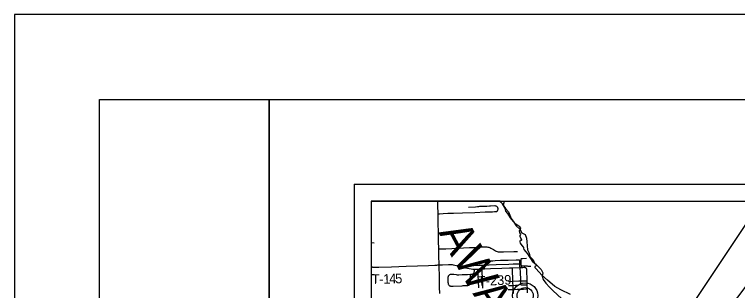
# Model space of a CAD drawing. Extents: x -12 to 34, y 0 to 22.
# Drawn here: x 0 to 4.257, y 20.374 to 22 of the extents above; entities that cross this region are included whole.
import ezdxf

# ---------------------------------------------------------------- set-up
doc = ezdxf.new("R2010")
doc.units = 0
for name, color, linetype in [('GM_X_Adjacent_County', 7, 'Continuous'), ('GM_X_Airport_Location_Class_2', 7, 'Continuous'), ('GM_X_County', 7, 'Continuous'), ('GM_X_County_Road_Text', 7, 'Continuous'), ('GM_X_Interstate_Location', 7, 'Continuous'), ('GM_X_Major_Lake', 7, 'Continuous'), ('GM_X_Major_Lake_Text', 7, 'Continuous'), ('GM_X_Major_River', 7, 'Continuous'), ('GM_X_Minor_River', 7, 'Continuous'), ('GM_X_Section', 7, 'Continuous'), ('GM_X_Township', 7, 'Continuous')]:
    doc.layers.add(name, color=color, linetype=linetype)

msp = doc.modelspace()

# ---------------------------------------------------------------- linework, layer by layer
at = {"layer": 'GM_X_Adjacent_County'}
msp.add_lwpolyline([(4.3077, 20.7695), (2.2584, 17.6954), (4.3077, 20.4)], close=True, dxfattribs=at)
at = {"layer": 'GM_X_Airport_Location_Class_2'}
for points in [[(3.2743, 20.3512), (3.2166, 20.3788), (3.1826, 20.399), (3.1387, 20.4357), (3.1057, 20.4645), (3.0716, 20.5015), (3.0667, 20.5084), (3.0652, 20.5149), (3.0677, 20.5194), (3.071, 20.5207), (3.0723, 20.5292), (3.0682, 20.5291), (3.0632, 20.5325), (3.0539, 20.5406), (3.0218, 20.5914), (3.0129, 20.6024), (3.0017, 20.617), (2.9993, 20.6241), (2.9999, 20.6294), (2.9947, 20.6323), (2.9798, 20.6534), (2.9773, 20.6606), (2.9773, 20.6665), (2.9789, 20.671), (2.9828, 20.6723), (2.9848, 20.6696), (2.9878, 20.671), (2.9848, 20.6775), (2.9773, 20.6905), (2.9771, 20.7009), (2.9804, 20.7014), (2.9819, 20.7063), (2.9761, 20.7139), (2.9738, 20.7278), (2.9789, 20.7331), (2.9817, 20.7408), (2.9754, 20.7494), (2.9529, 20.7652), (2.9376, 20.7806), (2.9215, 20.8031), (2.9049, 20.8288), (2.8931, 20.8413), (2.8916, 20.8525), (2.8855, 20.8653), (2.8738, 20.8847), (2.8638, 20.8955), (2.8606, 20.9), (2.1, 20.9), (2.1, 15.613)], [(3.2743, 20.3512), (3.2166, 20.3788), (3.1826, 20.399), (3.1387, 20.4357), (3.1057, 20.4645), (3.0716, 20.5015), (3.0667, 20.5084), (3.0652, 20.5149), (3.0677, 20.5194), (3.071, 20.5207), (3.0723, 20.5292), (3.0682, 20.5291), (3.0632, 20.5325), (3.0539, 20.5406), (3.0218, 20.5914), (3.0129, 20.6024), (3.0017, 20.617), (2.9993, 20.6241), (2.9999, 20.6294), (2.9947, 20.6323), (2.9798, 20.6534), (2.9773, 20.6606), (2.9773, 20.6665), (2.9789, 20.671), (2.9828, 20.6723), (2.9848, 20.6696), (2.9878, 20.671), (2.9848, 20.6775), (2.9773, 20.6905), (2.9771, 20.7009), (2.9804, 20.7014), (2.9819, 20.7063), (2.9761, 20.7139), (2.9738, 20.7278), (2.9789, 20.7331), (2.9817, 20.7408), (2.9754, 20.7494), (2.9529, 20.7652), (2.9376, 20.7806), (2.9215, 20.8031), (2.9049, 20.8288), (2.8931, 20.8413), (2.8916, 20.8525), (2.8855, 20.8653), (2.8738, 20.8847), (2.8638, 20.8955), (2.8606, 20.9), (2.1, 20.9), (2.1, 17.9664)]]:
    msp.add_lwpolyline(points, dxfattribs=at)
at = {"layer": 'GM_X_County'}
for points in [[(0.5, 21.5), (1.5, 21.5), (1.5, 0.5), (0.5, 0.5)], [(1.5, 21.5), (33.5, 21.5), (33.5, 0.5), (1.5, 0.5)]]:
    msp.add_lwpolyline(points, close=True, dxfattribs=at)
at = {"layer": 'GM_X_Interstate_Location'}
for radius in [0.0744, 0.0472]:
    msp.add_circle((3.0069, 20.345), radius, dxfattribs=at)
at = {"layer": 'GM_X_Major_Lake'}
msp.add_lwpolyline([(2.5037, 20.3569), (2.5028, 20.3942), (2.502, 20.447), (2.5004, 20.5249), (2.5002, 20.5371), (2.4993, 20.5682), (2.4984, 20.6191), (2.4976, 20.6645), (2.4961, 20.7203), (2.4954, 20.7668), (2.4943, 20.8263), (2.4934, 20.8751), (2.4929, 20.9)], dxfattribs=at)
at = {"layer": 'GM_X_Major_River'}
for p, q in [((2.1, 20.6568), (2.1189, 20.6561)), ((2.9316, 20.5081), (2.9768, 20.5103)), ((2.9768, 20.5103), (2.9849, 20.5106)), ((2.9093, 20.4037), (2.9358, 20.4044)), ((2.9369, 20.3813), (2.9358, 20.4044)), ((3.0166, 20.4324), (3.0176, 20.4089)), ((3.0176, 20.4089), (3.0186, 20.3839)), ((2.9072, 20.3802), (2.9369, 20.3813))]:
    msp.add_line(p, q, dxfattribs=at)
for points in [[(2.4943, 20.8263), (2.5022, 20.8268), (2.5238, 20.8282), (2.5517, 20.8293), (2.5858, 20.83), (2.6384, 20.8322), (2.7097, 20.8344), (2.7717, 20.8375), (2.7995, 20.8384), (2.815, 20.8387), (2.8274, 20.839), (2.8336, 20.8394), (2.8366, 20.8399), (2.8392, 20.8407), (2.8408, 20.8417), (2.8421, 20.8426), (2.8432, 20.8438), (2.8442, 20.8449), (2.8453, 20.8464), (2.8462, 20.8484), (2.847, 20.8504), (2.8474, 20.8535), (2.8474, 20.8557), (2.8472, 20.8575), (2.8469, 20.8596), (2.8457, 20.8625), (2.844, 20.8651), (2.8419, 20.8674), (2.8395, 20.8693), (2.8368, 20.8708), (2.8339, 20.8718), (2.8308, 20.8723), (2.8277, 20.8724), (2.8029, 20.8711), (2.7968, 20.871), (2.7813, 20.8702), (2.7473, 20.8693), (2.738, 20.8686), (2.7319, 20.868), (2.7259, 20.8665), (2.7136, 20.8653), (2.6741, 20.8631)], [(2.4984, 20.6191), (2.5033, 20.6193), (2.5404, 20.6206), (2.6796, 20.6272), (2.7074, 20.6286), (2.729, 20.6294), (2.7537, 20.6309), (2.766, 20.6312), (2.7815, 20.6311), (2.7877, 20.6306), (2.7908, 20.6301), (2.7938, 20.6294), (2.7967, 20.6285), (2.7996, 20.6273), (2.8051, 20.6245), (2.8209, 20.6152), (2.8316, 20.6089), (2.8372, 20.6062), (2.8426, 20.6039), (2.8483, 20.6023), (2.8514, 20.6018), (2.8545, 20.6015), (2.8576, 20.6015), (2.8802, 20.6025), (2.94, 20.6043), (2.9553, 20.6044), (2.961, 20.604)], [(2.9845, 20.52), (2.9842, 20.5257), (2.9835, 20.5413), (2.9834, 20.5474), (2.9829, 20.5534), (2.9829, 20.5566), (2.983, 20.558), (2.9836, 20.5597), (2.9843, 20.5611), (2.9852, 20.5622), (2.9864, 20.5632), (2.9878, 20.5636), (2.9909, 20.5638), (3.0139, 20.5641)], [(2.1, 20.5161), (2.1, 20.5161), (2.1056, 20.514), (2.1085, 20.513), (2.1128, 20.5122), (2.1181, 20.5116), (2.1273, 20.5111), (2.1458, 20.5115), (2.2202, 20.5146), (2.3071, 20.5178), (2.3723, 20.5203), (2.4375, 20.5228), (2.4747, 20.5243), (2.4872, 20.5248), (2.4934, 20.5249), (2.5004, 20.5249)], [(2.5004, 20.5249), (2.521, 20.5255), (2.5551, 20.5269), (2.5644, 20.5274), (2.5707, 20.5274), (2.577, 20.527), (2.5832, 20.5262), (2.5924, 20.5244), (2.6135, 20.5193), (2.6278, 20.5158)], [(2.6278, 20.5158), (2.6314, 20.5176), (2.6347, 20.5187), (2.6379, 20.5194), (2.6413, 20.5199), (2.6491, 20.5204), (2.7057, 20.5225), (2.7367, 20.5232), (2.7614, 20.5242), (2.7704, 20.5247)], [(2.7675, 20.5018), (2.7676, 20.506), (2.7679, 20.51), (2.7687, 20.5161), (2.7698, 20.522), (2.7704, 20.5247)], [(2.7704, 20.5247), (2.7711, 20.5273), (2.7725, 20.5314), (2.774, 20.5346), (2.7754, 20.537), (2.7773, 20.539), (2.7793, 20.5408), (2.7822, 20.5426), (2.7855, 20.5443), (2.7906, 20.5463), (2.7969, 20.5482), (2.8017, 20.5494), (2.8062, 20.5499), (2.8163, 20.5503), (2.8302, 20.5509), (2.8611, 20.5523), (2.8797, 20.5532), (2.9073, 20.5542), (2.9537, 20.5556), (2.966, 20.556), (2.9715, 20.5558), (2.9723, 20.5557), (2.973, 20.5553), (2.9735, 20.5549)], [(2.7704, 20.5247), (2.7951, 20.526), (2.8357, 20.527), (2.9109, 20.5303), (2.9357, 20.531), (2.9719, 20.5325), (2.9755, 20.5326)], [(2.9755, 20.5326), (2.9748, 20.5504), (2.9747, 20.5519), (2.9744, 20.553), (2.974, 20.5541), (2.9735, 20.5549)], [(2.9768, 20.5103), (2.9763, 20.5134), (2.9758, 20.5182), (2.9758, 20.522), (2.9755, 20.5326)], [(2.6278, 20.5158), (2.6558, 20.5089), (2.677, 20.5041), (2.6891, 20.5018), (2.6983, 20.5005), (2.705, 20.5001), (2.706, 20.5)], [(2.706, 20.5), (2.7061, 20.4944), (2.7059, 20.4864), (2.7056, 20.4833), (2.7049, 20.4803), (2.7038, 20.4774), (2.7021, 20.4748), (2.7, 20.4726), (2.6974, 20.4708), (2.6946, 20.4696), (2.6917, 20.4688), (2.6886, 20.4683), (2.6855, 20.4681), (2.6843, 20.468)], [(2.706, 20.5), (2.7075, 20.4999), (2.7199, 20.5), (2.7288, 20.5003)], [(2.7288, 20.5003), (2.7537, 20.5012), (2.7633, 20.5016), (2.7675, 20.5018)], [(2.734, 20.3896), (2.7303, 20.464), (2.729, 20.4969), (2.7288, 20.5003)], [(2.7587, 20.3884), (2.7571, 20.4239), (2.7546, 20.4804), (2.7539, 20.4959), (2.7537, 20.5012)], [(2.7675, 20.5018), (2.8036, 20.5033), (2.8688, 20.5056), (2.9153, 20.5073), (2.9316, 20.5081)], [(2.9349, 20.4295), (2.9319, 20.5015), (2.9316, 20.5081)], [(2.9808, 20.4314), (2.9791, 20.4891), (2.9783, 20.5006), (2.9779, 20.5042), (2.9774, 20.5071), (2.9768, 20.5103)], [(2.9845, 20.52), (2.9882, 20.5201), (3.0068, 20.5204), (3.0131, 20.5205), (3.0154, 20.5202), (3.0174, 20.5199), (3.0191, 20.5192), (3.0221, 20.5182), (3.0251, 20.5176), (3.0282, 20.5172), (3.0313, 20.5171), (3.0402, 20.5173)], [(2.9849, 20.5106), (2.9847, 20.515), (2.9845, 20.52)], [(2.9849, 20.5106), (2.9927, 20.511), (3.001, 20.5113), (3.004, 20.5111), (3.0056, 20.5108), (3.0073, 20.5105), (3.0085, 20.51), (3.0099, 20.5093), (3.0106, 20.5087)], [(3.0106, 20.5087), (3.0113, 20.508), (3.0125, 20.5063), (3.0131, 20.5053), (3.0138, 20.5037), (3.014, 20.5018), (3.014, 20.4974), (3.0166, 20.4324)], [(2.6843, 20.468), (2.6669, 20.4676), (2.6359, 20.4662), (2.6173, 20.4656), (2.6081, 20.4658), (2.6019, 20.4663), (2.5866, 20.469), (2.5805, 20.4696), (2.5742, 20.4697), (2.5711, 20.4695), (2.5681, 20.469), (2.5651, 20.4683), (2.5623, 20.4671), (2.5597, 20.4654), (2.5574, 20.4633), (2.5555, 20.4608), (2.554, 20.4581), (2.5529, 20.4552), (2.5523, 20.4522), (2.552, 20.4491), (2.5521, 20.4429), (2.5523, 20.4243), (2.5528, 20.4181), (2.5534, 20.4151), (2.5544, 20.4122), (2.5558, 20.4094), (2.5576, 20.4069), (2.5598, 20.4047), (2.5624, 20.403), (2.5652, 20.4017), (2.5682, 20.4009), (2.5713, 20.4006), (2.5836, 20.4009), (2.6363, 20.4027), (2.6425, 20.4032), (2.6611, 20.4038), (2.6672, 20.4043), (2.6703, 20.4048), (2.6733, 20.4056), (2.6762, 20.4068), (2.6788, 20.4084), (2.6811, 20.4105), (2.683, 20.4129), (2.6844, 20.4156), (2.6854, 20.4186), (2.686, 20.4216), (2.6861, 20.4247), (2.6858, 20.4371), (2.6854, 20.4495), (2.6849, 20.4588), (2.6843, 20.468)], [(2.9087, 20.4285), (2.9323, 20.4294), (2.9349, 20.4295)], [(2.9349, 20.4295), (2.9703, 20.431), (2.9808, 20.4314)], [(2.9358, 20.4044), (2.9352, 20.4207), (2.9349, 20.4295)], [(2.9358, 20.4044), (2.9503, 20.4058), (2.962, 20.4066)], [(2.9808, 20.4314), (3.0131, 20.4323), (3.0166, 20.4324)], [(2.9819, 20.4074), (2.9816, 20.4087), (2.9812, 20.4146), (2.9808, 20.4314)], [(2.9819, 20.4074), (2.983, 20.4071), (3.0141, 20.4087), (3.0176, 20.4089)], [(2.9369, 20.3813), (2.9601, 20.3823), (2.9975, 20.3833), (3.013, 20.3838), (3.0186, 20.3839)], [(2.938, 20.3566), (2.9378, 20.3599), (2.9369, 20.3813)], [(3.0186, 20.3839), (3.0195, 20.3609), (3.0195, 20.3602)]]:
    msp.add_lwpolyline(points, dxfattribs=at)
at = {"layer": 'GM_X_Minor_River'}
for points in [[(2.8844, 20.9), (2.8842, 20.8983), (2.878, 20.8766), (2.8907, 20.8569)], [(2.8844, 20.9), (2.8842, 20.8983), (2.8781, 20.8766), (2.8907, 20.8569)], [(2.8907, 20.8569), (2.9093, 20.8379), (2.9176, 20.8181), (2.9252, 20.798), (2.94, 20.7767), (2.9544, 20.7554), (2.9749, 20.7353), (2.9882, 20.7148), (3.0076, 20.7038), (3.0156, 20.6829), (3.0167, 20.6604), (3.0178, 20.6384), (3.0216, 20.6148), (3.0308, 20.5943), (3.0346, 20.5753), (3.0532, 20.5544), (3.0615, 20.5347), (3.0812, 20.5179), (3.1006, 20.4986), (3.1116, 20.4788), (3.1071, 20.4594), (3.1139, 20.4385), (3.1283, 20.4176), (3.1496, 20.3937), (3.1705, 20.3747), (3.2225, 20.3249)]]:
    msp.add_lwpolyline(points, dxfattribs=at)
at = {"layer": 'GM_X_Section'}
msp.add_lwpolyline([(0, 0), (34, 0), (34, 22), (0, 22)], close=True, dxfattribs=at)
at = {"layer": 'GM_X_Township'}
for p, q in [((2, 21), (9, 21)), ((2, 21), (2, 14)), ((2.1, 20.9), (2.1, 14.1)), ((2.1, 20.9), (8.9, 20.9))]:
    msp.add_line(p, q, dxfattribs=at)

# ---------------------------------------------------------------- texts
at = {"layer": 'GM_X_County_Road_Text'}
for s, height, rotation, p in [('T', 0.0568, 358.6628, (2.1029, 20.4144)), ('-', 0.0568, 1.437, (2.1483, 20.4134)), ('1', 0.0568, 1.8935, (2.1722, 20.414)), ('4', 0.0568, 2.0927, (2.2074, 20.4152)), ('5', 0.0568, 2.1345, (2.2424, 20.4164)), ('T-239', 0.05682, 2.5133, (2.7289, 20.4014))]:
    msp.add_text(s, height=height, rotation=rotation, dxfattribs=at).set_placement(p)
at = {"layer": 'GM_X_Major_Lake_Text'}
for s, rotation, p in [('A', 298.12, (2.4957, 20.7168)), ('W', 299.2857, (2.5767, 20.5654)), ('A', 305.1593, (2.6948, 20.3571))]:
    msp.add_text(s, height=0.1894, rotation=rotation, dxfattribs=at).set_placement(p)

doc.saveas('drawing.dxf')
